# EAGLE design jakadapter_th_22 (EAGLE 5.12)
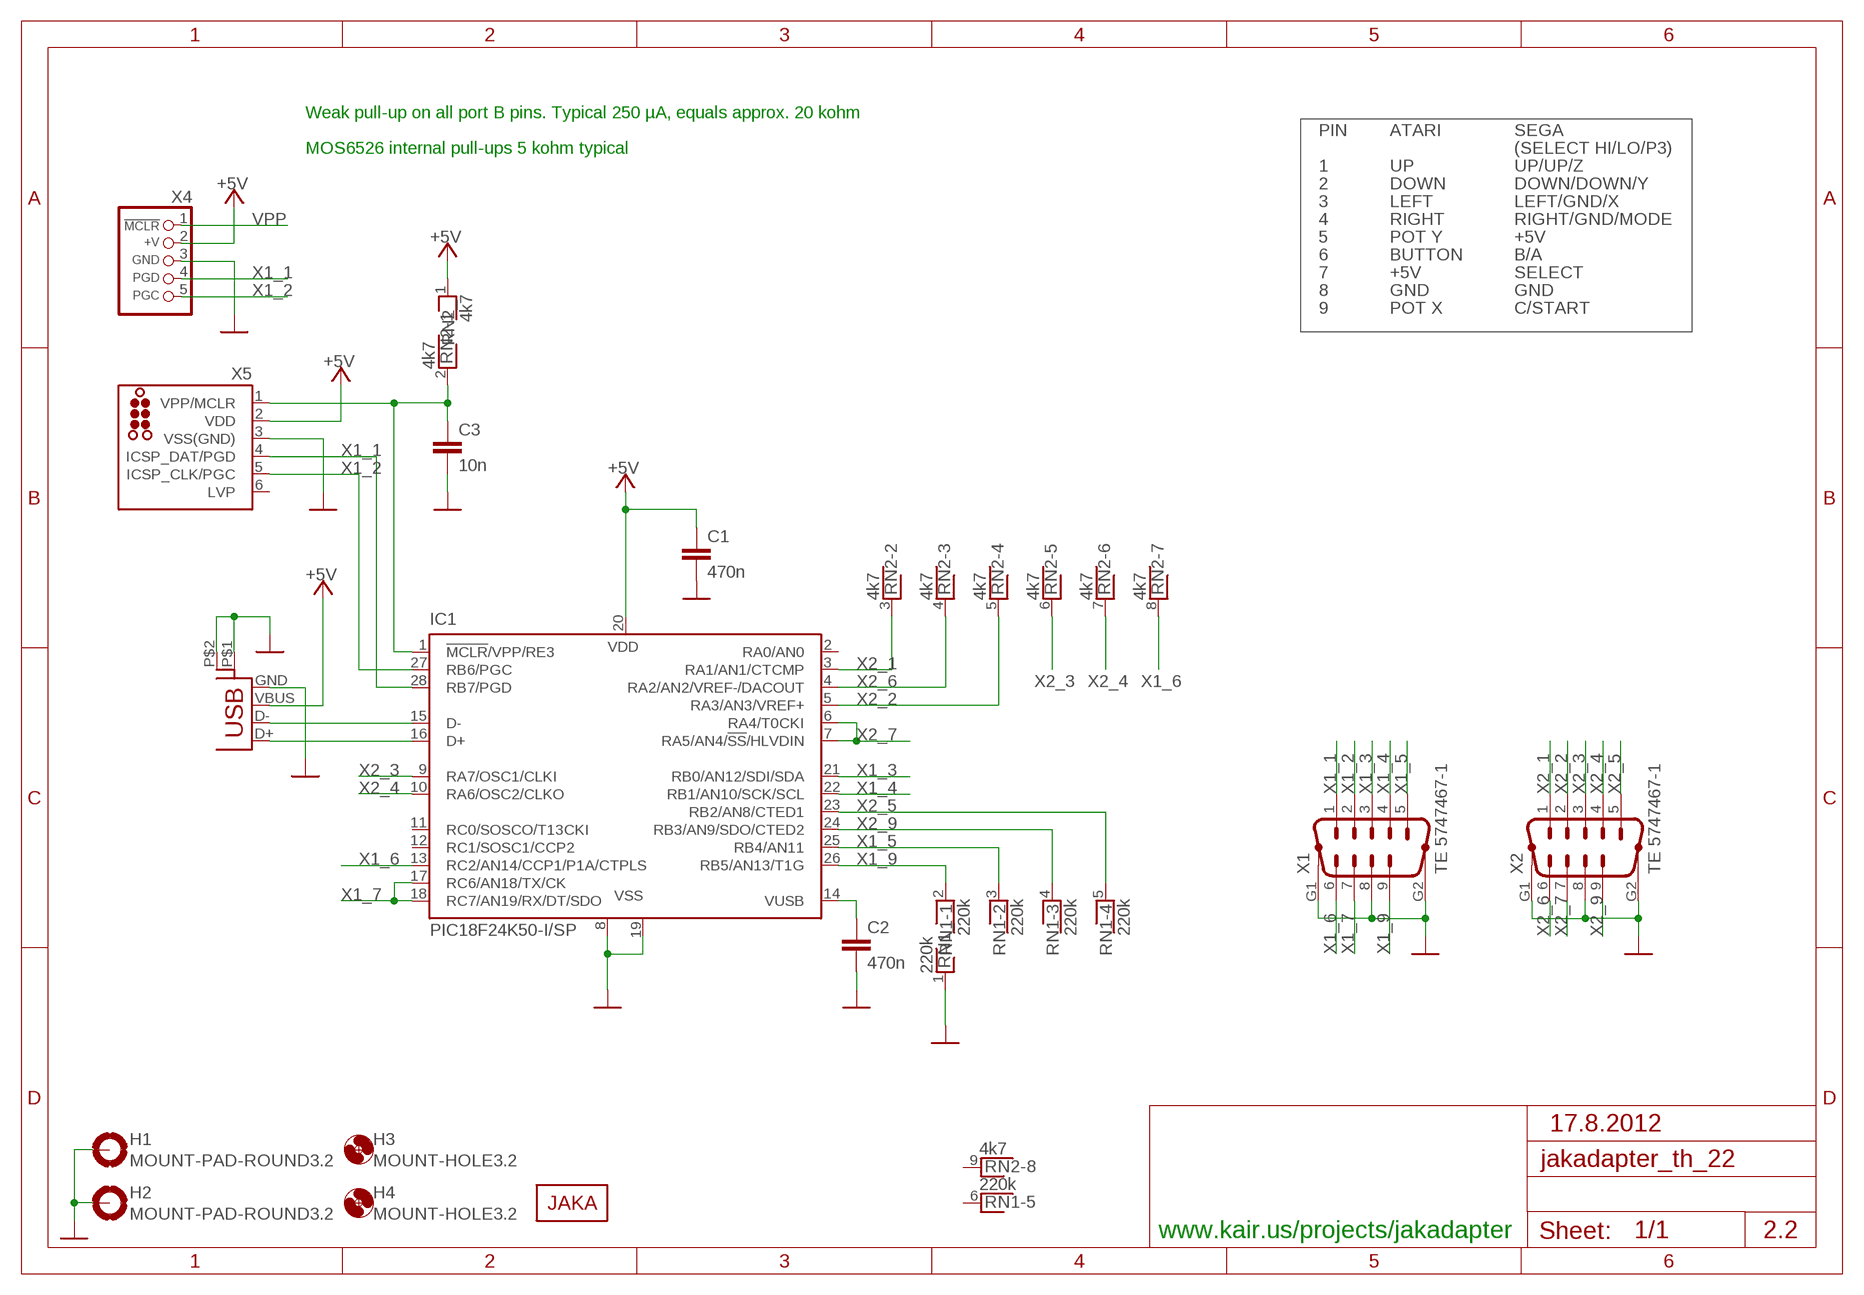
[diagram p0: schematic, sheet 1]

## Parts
C1  470n  C-EU050-024X044  [C050-024X044]
C2  470n  C-EU050-024X044  [C050-024X044]
C3  10n  C-EU050-024X044  [C050-024X044]
H1  MOUNT-PAD-ROUND3.2  [3,2-PAD]
H2  MOUNT-PAD-ROUND3.2  [3,2-PAD]
H3  MOUNT-HOLE3.2  [3,2]
H4  MOUNT-HOLE3.2  [3,2]
IC1  PIC18F24K50-I/SP  PIC18F2X50-I/SP  [DIL28-3]
RN1  220k  RNX5  [RN-6]
RN2  4k7  RNX8  [RN-9]
U$1  JAKA_LOGO_SILK_NANO  [JAKA_SILK_NANO]
X1  TE 5747467-1  M09HP-PLASTIC  [M09H_PLASTIC]
X2  TE 5747467-1  M09HP-PLASTIC  [M09H_PLASTIC]
X3  USB_B_PTH  [SPARKFUN_USB-B-PTH]
X4  CON_HEADER_PRG_PIC_ICSPB  [HEADER_PRG_1X05_ICSP_B]
X5  TC2030-MCP-NL-JKA  [TC2030-MCP-NL-JKA]

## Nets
+5V: C1.1 IC1.20(VDD) RN2.1 X3.VBUS X4.2(+V) X5.2(VDD)
GND: C1.2 C2.2 C3.2 H1.B3,2(MOUNT) H2.B3,2(MOUNT) IC1.8(VSS) IC1.19(VSS) RN1.1 X1.8 X1.G1 X1.G2 X2.8 X2.G1 X2.G2 X3.GND X3.P$1(SHIELD) X3.P$2(SHIELD1) X4.3(GND) X5.3(VSS(GND))
N$3: C2.1 IC1.14(VUSB)
N$6: IC1.15(D-) X3.D-
N$16: IC1.16(D+) X3.D+
VPP: C3.1 IC1.1(!MCLR!/VPP/RE3) RN2.2 X4.1(/MCLR) X5.1(VPP/MCLR)
X1_1: IC1.28(RB7/PGD) X1.1 X4.4(PGD) X5.4(ICSP_DAT/PGD)
X1_2: IC1.27(RB6/PGC) X1.2 X4.5(PGC) X5.5(ICSP_CLK/PGC)
X1_3: IC1.21(RB0/AN12/SDI/SDA) X1.3
X1_4: IC1.22(RB1/AN10/SCK/SCL) X1.4
X1_5: IC1.25(RB4/AN11) RN1.3 X1.5
X1_6: IC1.13(RC2/AN14/CCP1/P1A/CTPLS) RN2.8 X1.6
X1_7: IC1.17(RC6/AN18/TX/CK) IC1.18(RC7/AN19/RX/DT/SDO) X1.7
X1_9: IC1.26(RB5/AN13/T1G) RN1.2 X1.9
X2_1: IC1.3(RA1/AN1/CTCMP) RN2.3 X2.1
X2_2: IC1.5(RA3/AN3/VREF+) RN2.5 X2.2
X2_3: IC1.9(RA7/OSC1/CLKI) RN2.6 X2.3
X2_4: IC1.10(RA6/OSC2/CLKO) RN2.7 X2.4
X2_5: IC1.23(RB2/AN8/CTED1) RN1.5 X2.5
X2_6: IC1.4(RA2/AN2/VREF-/DACOUT) RN2.4 X2.6
X2_7: IC1.6(RA4/T0CKI) IC1.7(RA5/AN4/!SS!/HLVDIN) X2.7
X2_9: IC1.24(RB3/AN9/SDO/CTED2) RN1.4 X2.9
Unconnected: IC1.2(RA0/AN0) IC1.11(RC0/SOSCO/T13CKI) IC1.12(RC1/SOSC1/CCP2) RN1.6 RN2.9 X5.6(LVP)

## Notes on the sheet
- Weak pull-up on all port B pins. Typical 250 µA, equals approx. 20 kohm
- PIN | ATARI | SEGA
- MOS6526 internal pull-ups 5 kohm typical | (SELECT HI/LO/P3)
- 1 | UP | UP/UP/Z
- 2 | DOWN | DOWN/DOWN/Y
- 3 | LEFT | LEFT/GND/X
- 4 | RIGHT | RIGHT/GND/MODE
- 5 | POT Y | +5V
- 6 | BUTTON | B/A
- 7 | +5V | SELECT
- 8 | GND | GND
- 9 | POT X | C/START
- 17.8.2012
- www.kair.us/projects/jakadapter | 2.2

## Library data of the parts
C1-C3 = dual_atari:C-EU: CAPACITOR, European symbol
H1 H2 = dual_atari:MOUNT-PAD-ROUND: MOUNTING PAD, round
H3 H4 = dual_atari:MOUNT-HOLE: MOUNTING HOLE with drill center marker
IC1 = dual_atari:PIC18F2X50
RN1 = dual_atari:RNX5: RESISTOR NETWORK; OC_FARNELL: unknown; OC_NEWARK: unknown
RN2 = dual_atari:RNX8: RESISTOR NETWORK; OC_FARNELL: unknown; OC_NEWARK: unknown
U$1 = dual_atari:JAKA_LOGO
X1 X2 = dual_atari:M09HP: SUB-D
X3 = dual_atari:USB_B_PTH
X4 = omat:CON_HEADER_PRG_PIC_ICSP: 5-pin PIC In Circuit Serial Programming header
X5 = dual_atari:TC2030: TAG-CONNECT ISP Connector Manufacturer: Tag-Connect Cable for easy In-Circuit PCB Programming. Designed for Microchip ICD2, suitable for many others. Two variants - one "with legs" (for hads-free fit on PCB) and another "without legs" for quick programming. PADDescription 1MCLR/Vpp 2Vdd 3GND 4PGD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

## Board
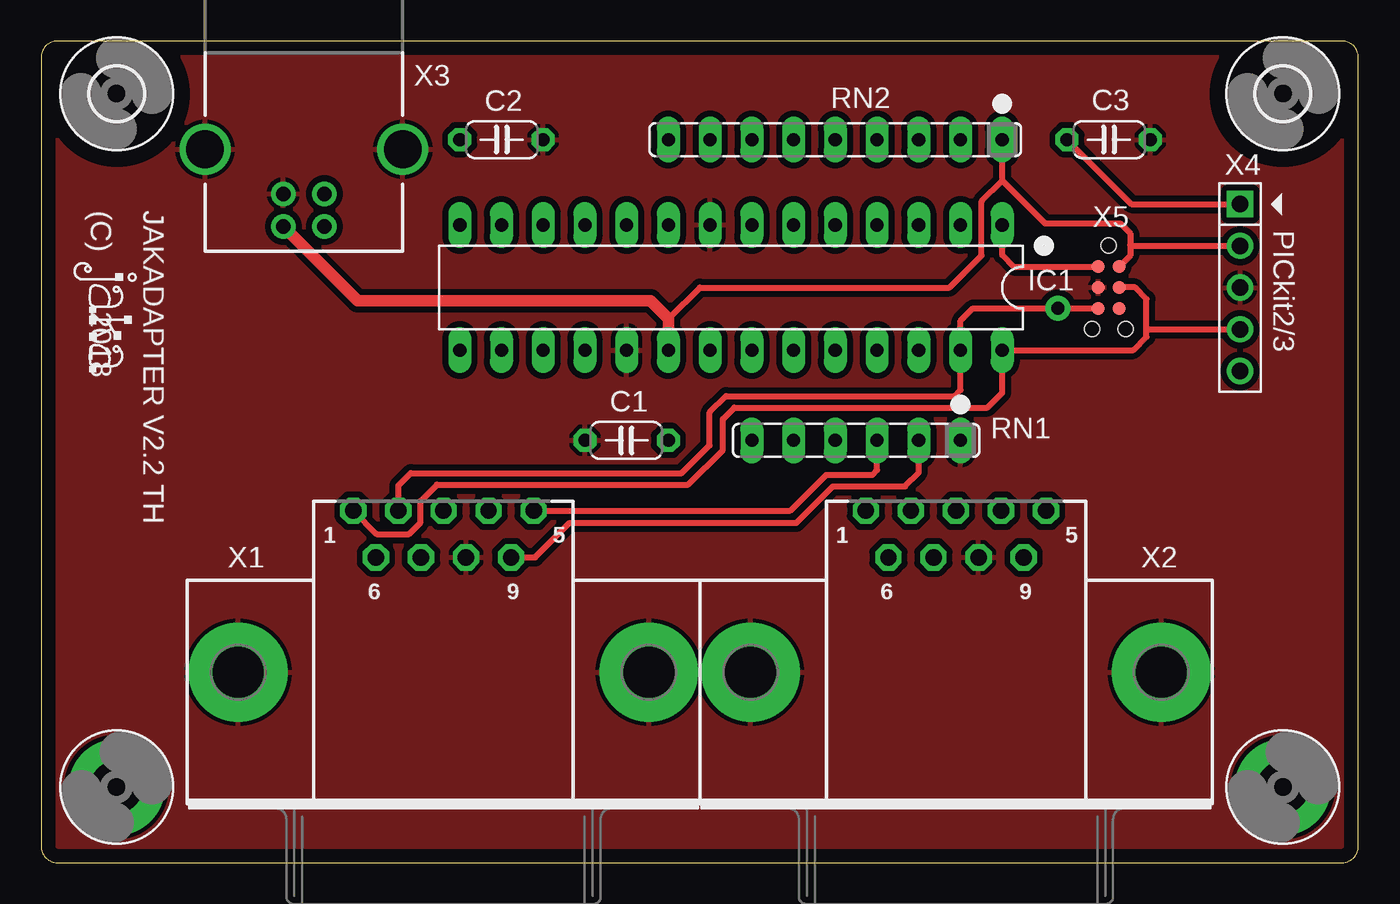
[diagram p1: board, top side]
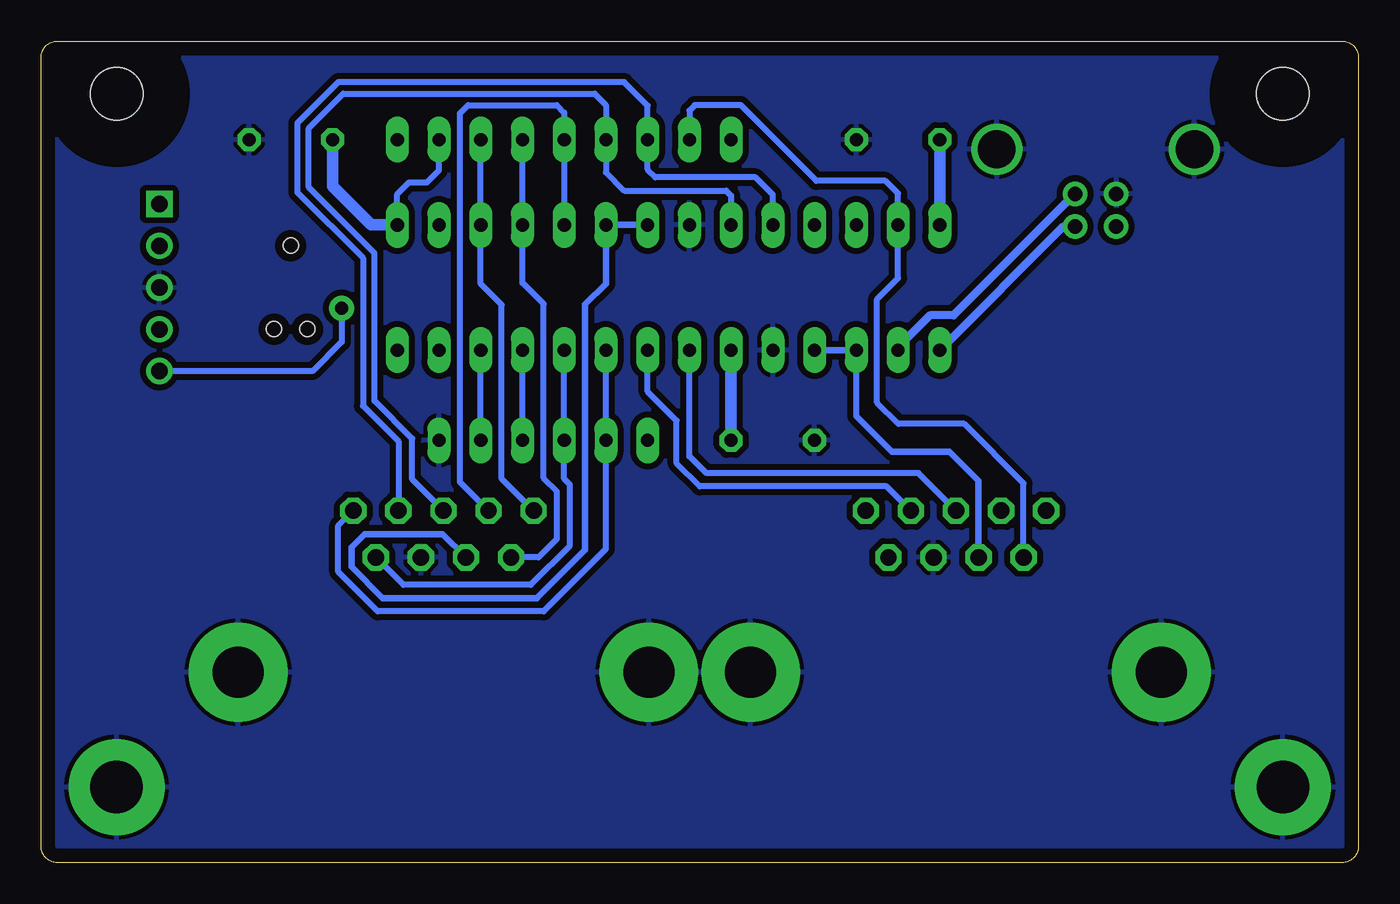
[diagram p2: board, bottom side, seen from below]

Size 80.2 x 50 mm. Coordinates in mm from the lower left corner, seen from the top.
Outline: 79.2,0 arc90 80.2,1 80.2,49 arc90 79.2,50 1,50 arc90 0,49 0,1 arc90 1,0 79.2,0
Copper layers (1*16): Top 0.035mm / dielectric 1.1mm / Bottom 0.035mm
Design rules "ITEADstudio_DRC *": minimum track width 0.3mm, minimum drill 0.6mm, track to track 0.35mm, track to pad 0.35mm, pad to pad 0.35mm, via to via 0.35mm, smd to smd 0mil, copper to edge 0.5mm, drill to drill 0.25mm, minimum pad ring 0.3mm, minimum via ring 0.3mm, stop-mask expansion 2mil, vias tented up to drill 100mil, thermal gap 10mil
tRestrict: area 3.2,3.2 to 6,6; area 74.2,3.2 to 77,6
bRestrict: area 3.2,3.2 to 6,6; area 74.2,3.2 to 77,6

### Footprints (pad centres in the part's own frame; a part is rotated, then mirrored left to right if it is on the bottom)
C050-024X044 = drill 0.8 octagon: 1 -2.54,0; 2 2.54,0
3,2-PAD = drill 3.2 pad 5.842 round: B3,2 0,0
3,2 = hole 3.2: 0,0
DIL28-3 = drill 0.8 long: 1 -16.51,-3.81; 2 -13.97,-3.81; 3 -11.43,-3.81; 4 -8.89,-3.81; 5 -6.35,-3.81; 6 -3.81,-3.81; 7 -1.27,-3.81; 8 1.27,-3.81; 9 3.81,-3.81; 10 6.35,-3.81; 11 8.89,-3.81; 12 11.43,-3.81; 13 13.97,-3.81; 14 16.51,-3.81; 15 16.51,3.81; 16 13.97,3.81; 17 11.43,3.81; 18 8.89,3.81; 19 6.35,3.81; 20 3.81,3.81; 21 1.27,3.81; 22 -1.27,3.81; 23 -3.81,3.81; 24 -6.35,3.81; 25 -8.89,3.81; 26 -11.43,3.81; 27 -13.97,3.81; 28 -16.51,3.81
RN-6 = drill 0.8 long: 1 -6.35,0; 2 -3.81,0; 3 -1.27,0; 4 1.27,0; 5 3.81,0; 6 6.35,0
RN-9 = drill 0.8 long: 1 -10.16,0; 2 -7.62,0; 3 -5.08,0; 4 -2.54,0; 5 0,0; 6 2.54,0; 7 5.08,0; 8 7.62,0; 9 10.16,0
M09H_PLASTIC = drill 1 octagon: 1 -5.486,1.42; 2 -2.743,1.42; 3 0,1.42; 4 2.743,1.42; 5 5.486,1.42; 6 -4.115,-1.42; 7 -1.372,-1.42; 8 1.372,-1.42; 9 4.115,-1.42 | drill 3.1 pad 6 round: G1 -12.5,-8.41; G2 12.5,-8.41
SPARKFUN_USB-B-PTH = drill 0.9 round: D+ 0,1.25; D- 1.981,1.25; GND 0,-1.25; VBUS 1.981,-1.25 | drill 2.3 round: P$1 -2.718,-6.02; P$2 -2.718,6.02
HEADER_PRG_1X05_ICSP_B = drill 1 square: 1 -5.08,0 | drill 1 round: 2 -2.54,0; 3 0,0; 4 2.54,0; 5 5.08,0
TC2030-MCP-NL-JKA = smd 0.787 x 0.787: 1 1.27,-0.635; 2 1.27,0.635; 3 2.54,-0.635; 4 2.54,0.635; 5 3.81,-0.635; 6 3.81,0.635 | hole 0.9: 0,0; 5.08,-1.016; 5.08,1.016

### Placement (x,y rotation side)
C1  35.65,25.7 180 top
C2  28.03,44 0 top
C3  65,44 0 top
H1  75.6,4.6 0 top
H2  4.6,4.6 0 top
H3  4.6,46.8 0 top
H4  75.6,46.8 0 top
IC1  42,35 180 top
RN1  49.62,25.7 180 top
RN2  48.35,44 180 top
U$1  3.9,33.2 270 top
X1  24.5,20 0 top
X2  55.7,20 0 top
X3  16,40.7 270 top
X4  73,35 270 top
X5  65,37.55 270 top

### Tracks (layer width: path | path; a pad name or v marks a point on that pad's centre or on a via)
+5V
  Top 0.35: 38.19,33.09 40.1,35 55.3,35 57.25,36.95 57.25,40.25 58.51,41.51 | 58.51,41.51 RN2.1 | 58.51,41.51 61.12,38.9 65.7,38.9 66.3,38.3 66.3,37.6 | X5.2 66.3,36.95 66.3,37.6 | X4.2 66.36,37.54 66.3,37.6
  Top 0.7: X3.VBUS 19.27,34.2 37.1,34.2 38.19,33.11 38.19,33.09 IC1.20
  Bottom 0.7: IC1.20 C1.1
GND
  pour Bottom (isolate 0.37): 1,49 1,1 79.2,1 79.2,49
  pour Top (isolate 0.37): 1,49 1,1 79.2,1 79.2,49
N$3
  Bottom 0.7: IC1.14 C2.1
N$6
  Bottom 0.5: X3.D- 17.96,38.72 IC1.15
N$16
  Bottom 0.5: X3.D+ 24.65,33.3 26.1,33.3 28.03,31.37 IC1.16
VPP
  Top 0.35: X5.1 59.22,36.28 58.51,36.99 IC1.1 | C3.1 66.38,40.08 X4.1
  Bottom 0.35: RN2.2 55.97,42.13 56.7,41.4 57.8,41.4 58.51,40.69 IC1.1
  Bottom 0.7: C3.1 62.46,41.16 60.11,38.81 IC1.1
X1_1
  Top 0.35: X1.1 20.43,20 22.4,20 23.1,20.7 23.1,22 24.1,23 39.4,23 41.5,25.1 41.5,27 42.2,27.7 57.62,27.7 58.51,28.59 IC1.28 66.49,31.19 67.3,32 67.3,32.46 | 67.3,32.46 67.3,34.3 66.59,35.01 X5.4 | 67.3,32.46 X4.4
X1_2  (via drill 0.8 pad 1.5)
  Top 0.35: X1.2 21.76,22.96 22.5,23.7 39,23.7 40.7,25.4 40.7,27.4 41.7,28.4 55.6,28.4 55.97,28.77 IC1.27 55.97,32.97 56.74,33.74 v61.9,33.74 X5.5
  Bottom 0.35: v61.9,33.74 61.9,31.7 63.68,29.92 X4.5
X1_3
  Bottom 0.35: IC1.21 40.73,24.73 39.7,23.7 26.78,23.7 X1.3
X1_4
  Bottom 0.35: X1.4 28.72,22.9 40.1,22.9 41.5,24.3 41.5,26.9 43.27,28.67 IC1.22
X1_5
  Top 0.35: RN1.3 50.9,23.9 50.6,23.6 47.8,23.6 45.62,21.42 X1.5
  Bottom 0.35: RN1.3 IC1.25
X1_6
  Bottom 0.35: X1.6 20.39,23.09 24,26.7 28,26.7 29.3,28 29.3,34.3 28.03,35.57 IC1.13 28.03,40.73 28.8,41.5 33,41.5 37.6,46.1 40.4,46.1 40.73,45.77 RN2.8
X1_7
  Bottom 0.35: 28.4,25 30.57,27.17 IC1.17
  Bottom 0.4: X1.7 23.13,23.23 24.9,25 28.4,25 | IC1.17 IC1.18
X1_9
  Top 0.35: RN1.2 53.43,23.73 52.6,22.9 48.2,22.9 45.98,20.68 32.18,20.68 30.08,18.58 X1.9
  Bottom 0.35: RN1.2 IC1.26
X2_1
  Bottom 0.35: RN2.3 IC1.3 53.43,35.23 52.15,33.95 52.15,23.36 X2.1
X2_2
  Bottom 0.35: IC1.5 RN2.5 48.35,45.65 48.8,46.1 54.2,46.1 54.7,45.6 54.7,23.16 X2.2
X2_3
  Bottom 0.35: X2.3 57.6,23.32 57.6,25.8 59.9,28.1 59.9,37.1 63.9,41.1 63.9,44.7 61.8,46.8 46.5,46.8 45.81,46.11 RN2.6 45.81,42.01 44.7,40.9 38.5,40.9 38.19,40.59 IC1.9
X2_4
  Bottom 0.35: X2.4 58.44,25.64 60.6,27.8 60.6,36.8 64.6,40.8 64.6,45 62.1,47.5 44.7,47.5 43.27,46.07 RN2.7 43.27,42.17 42.8,41.7 36.7,41.7 35.65,40.65 IC1.10
X2_5
  Bottom 0.35: IC1.23 RN1.5 45.81,19.09 49.6,15.3 59.7,15.3 62.1,17.7 62.1,20.51 X2.5
X2_6
  Bottom 0.35: RN2.4 IC1.4 50.89,35.29 49.6,34 49.6,23.4 48.8,22.6 48.8,19.7 49.92,18.58 X2.6
X2_7
  Bottom 0.35: 50,16.1 50,16.11 47.08,19.03
  Bottom 0.4: IC1.7 IC1.6 45.81,35.24 47.08,33.97 47.08,19.03 | X2.7 55.75,20 60.5,20 61.3,19.2 61.3,18 59.4,16.1 50,16.1
X2_9
  Bottom 0.35: IC1.24 RN1.4 48.35,23.35 48,23 48,19.3 50.4,16.9 58.13,16.9 X2.9

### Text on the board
tPlace: (C) 2018 | JAKADAPTER V2.2 TH | PICkit2/3
tStop: WWW.KAIR.US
